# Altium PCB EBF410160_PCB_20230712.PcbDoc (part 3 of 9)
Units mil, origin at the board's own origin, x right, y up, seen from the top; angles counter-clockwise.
Board outline 5393.69 x 3858.26 mil, 6 copper layers (TOP, GND02, ART03, POW04, GND05, BOTTOM), stack 47.2 mil thick; 572 components, 434 nets, 2057 pads, 1177 vias.
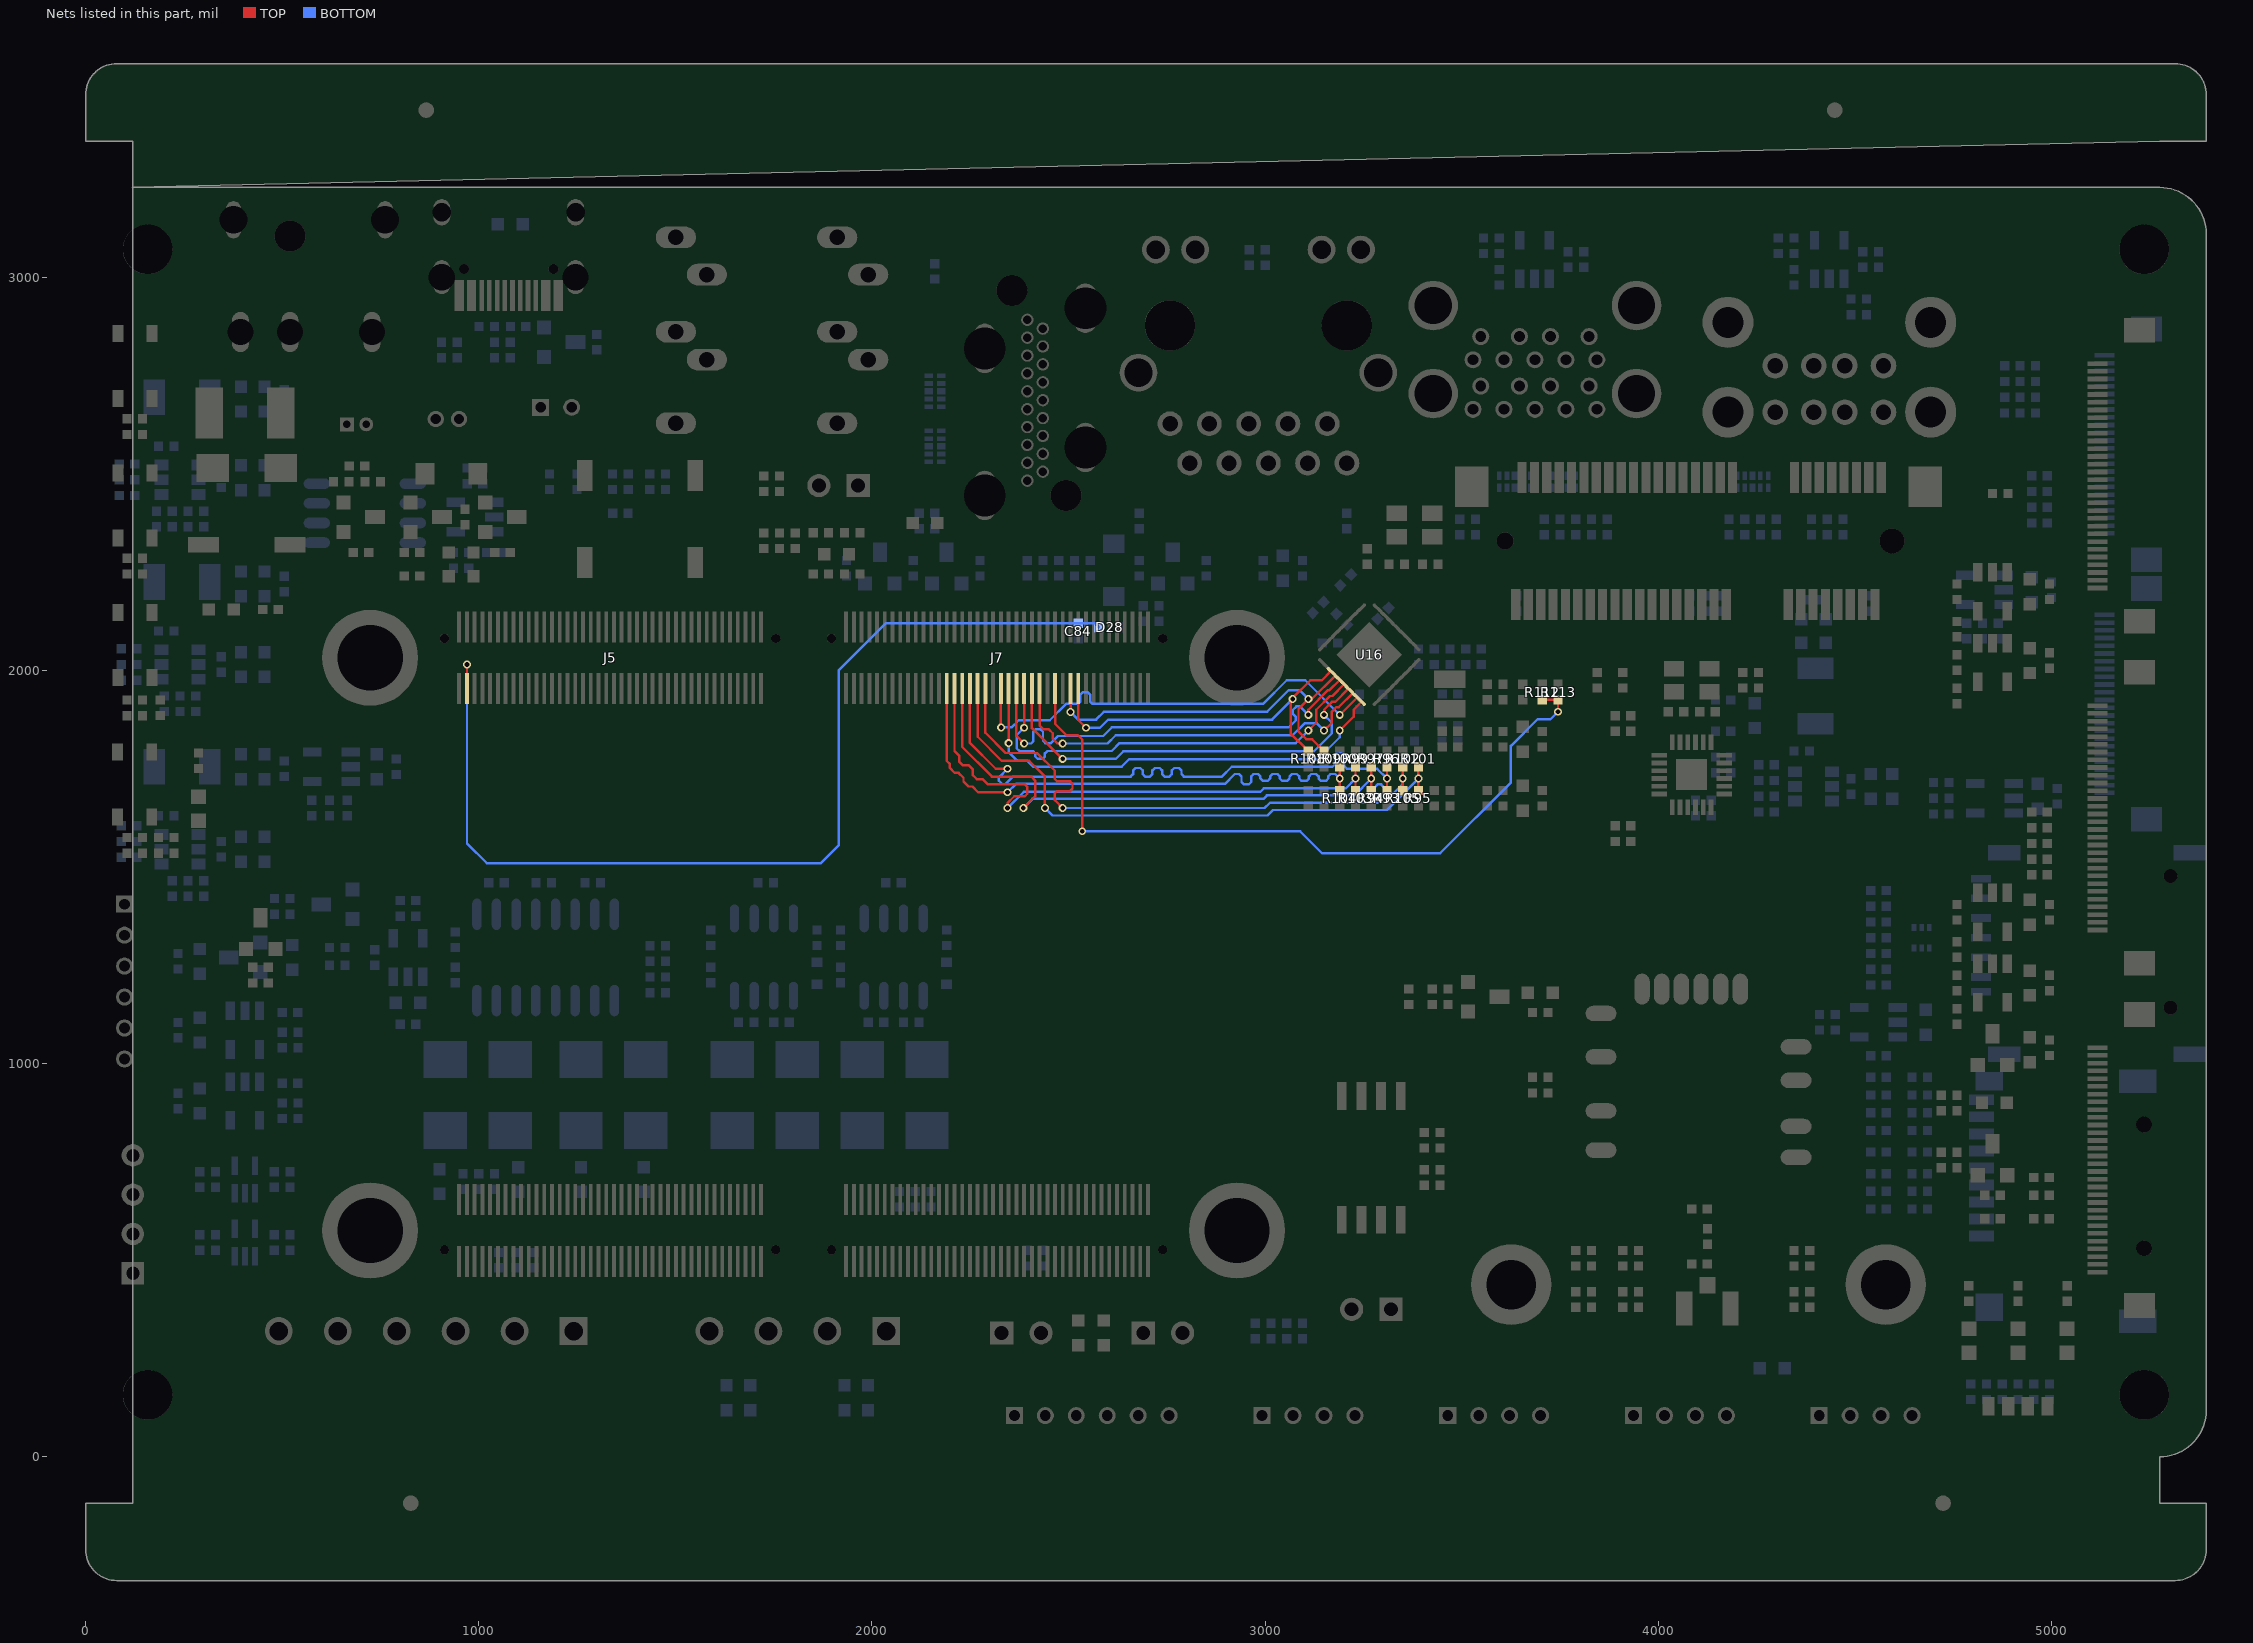
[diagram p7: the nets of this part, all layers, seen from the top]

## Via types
v1: diameter 20, hole 12, TOP to BOTTOM, 1177 vias

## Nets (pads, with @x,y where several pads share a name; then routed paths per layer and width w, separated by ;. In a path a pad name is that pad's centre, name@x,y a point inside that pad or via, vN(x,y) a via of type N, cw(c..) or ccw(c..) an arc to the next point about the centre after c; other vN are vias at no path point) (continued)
GMAC1_MCLKINOUT_M1: J7.56 R112.1 R113.1 | length 1915.2
  TOP w6.16: J7.56@2465.75,1953.5 2465.75,1864.25 2494.95,1835.05 2523.84,1835.05 2535,1823.89 v1(2535,1591) ; R112.1@3705,1925.32 R113.1@3745,1925.32 v1(3745,1895)
  BOTTOM w6.16: v1(2535,1591) 3089,1591 3145,1535 3445,1535 3625,1715 3625,1808.02 3692.91,1875.92 3725.92,1875.92 v1(3745,1895)
GMAC1_MDC_M1: J7.62 R108.2 U16.13 | length 945.1
  TOP w6.16: J7.62@2524.8,1953.5 2524.8,1873.82 v1(2544.49,1854.13) ; R108.2@3110,1794.68 3065,1839.68 3065,1922.05 v1(3070,1927.05) 3070,1930 3115,1975 3144.32,1975 U16.13@3167.56,1998.24
  BOTTOM w6.16: v1(2544.49,1854.13) 2580,1854.13 2600.87,1875 3017.95,1875 v1(3070,1927.05)
GMAC1_MDIO_M1: J7.60 R109.2 U16.14 | length 984.6
  TOP w6.16: v1(2505.12,1894.13) J7.60@2505.12,1953.5 ; R109.2@3150,1794.68 3119.68,1825 3105,1825 3085,1845 3085,1902.05 v1(3110,1927.05) 3118.65,1927.05 U16.14@3178.7,1987.1
  BOTTOM w6.16: v1(2505.12,1894.13) 2524.25,1875 2570,1875 2590,1895 3005,1895 3060,1950 3087.05,1950 v1(3110,1927.05)
GMAC1_RSTN: C84.1 D28.1 J5.4 | length 2661.6
  TOP w6.16: J5.4@969.68,1953.5 969.68,1979.68 970,1980 v1(970,2015)
  BOTTOM w6.16: v1(970,2015) 970,1560 1020,1510 1870,1510 1915,1555 1915,2000 2034.68,2119.68 C84.1@2525,2119.68 2567.37,2119.68 D28.1@2577.05,2110
GMAC1_RXCLK_M1: J7.36 R95.2 R101.1 | length 1472.9
  TOP w6.16: J7.36@2268.9,1953.5 2268.9,1831.1 2330,1770 2400,1770 2440,1730 v1(2440,1650) ; R95.2@3390,1694.68 v1(3390,1725) R101.1@3390,1755.32
  BOTTOM w6.16: v1(2440,1650) 2459.08,1630.92 3005.92,1630.92 3020,1645 3310,1645 v1(3390,1725)
GMAC1_RXD0_M1: J7.34 R93.2 R96.1 | length 1528.3
  TOP w6.16: J7.34@2249.21,1953.5 2249.21,1815.79 2315,1750 v1(2345,1750) ; R93.2@3310,1694.68 v1(3310,1725) R96.1@3310,1755.32
  BOTTOM w6.16: v1(2345,1750) 2322.94,1727.94 2322.94,1719.23 2331.16,1711.01 2339.87,1711.01 2358.86,1730 2657.92,1730 2664.08,1736.16 2664.08,1745.62 2670.24,1751.78 2682.56,1751.78 2688.72,1745.62 2688.72,1736.16 2694.88,1730 2707.2,1730 2713.36,1736.16 2713.36,1745.62 2719.52,1751.78 2731.84,1751.78 2738,1745.62 2738,1736.16 2744.16,1730 2756.48,1730 2762.64,1736.16 2762.64,1745.62 2768.8,1751.78 2781.12,1751.78 2787.28,1745.62 2787.28,1736.16 2793.44,1730 2890,1730 2915,1755 3171.14,1755 3177.3,1761.16 3177.3,1783.84 3183.45,1790 3195.78,1790 3201.93,1783.84 3201.93,1756.16 3208.09,1750 3285,1750 v1(3310,1725)
GMAC1_RXD1_M1: J7.32 R94.2 R97.1 | length 1428
  TOP w6.16: J7.32@2229.53,1953.5 2229.53,1805.47 2305,1730 2405,1730 2415,1720 2415,1680 v1(2385,1650) ; R94.2@3270,1694.68 v1(3270,1725) R97.1@3270,1755.32
  BOTTOM w6.16: v1(2385,1650) 2408.04,1673.04 2995.77,1673.04 3004.69,1681.96 3226.96,1681.96 v1(3270,1725)
GMAC1_RXD2_M1: J7.30 R99.1 R103.1 | length 1465.9
  TOP w6.16: J7.30@2209.84,1953.5 2209.84,1795.16 2221.76,1783.24 2221.76,1768.24 2231.68,1758.32 2240.39,1758.32 2246.68,1758.32 2256.61,1748.39 2256.61,1733.4 2266.53,1723.47 2275.24,1723.47 2281.53,1723.47 2295,1710 2388.84,1710 2395,1703.84 2395,1686.16 2388.84,1680 2361.99,1680 2345,1663.02 v1(2345,1650) ; R103.1@3230,1694.68 v1(3230,1725) R99.1@3230,1755.32
  BOTTOM w6.16: v1(2345,1650) 2386.52,1691.52 2988.11,1691.52 2997.03,1700.44 3205.44,1700.44 v1(3230,1725)
GMAC1_RXD3_M1: J7.28 R100.1 R104.1 | length 1434.6
  TOP w6.16: J7.28@2190.16,1953.5 2190.16,1769.84 2198.05,1761.95 2198.05,1751.95 2210.47,1739.53 2220.47,1739.53 2232.9,1727.1 2232.9,1717.1 2245.32,1704.68 2255.32,1704.68 2270,1690 v1(2345,1690) ; R104.1@3190,1694.68 v1(3190,1725) R100.1@3190,1755.32
  BOTTOM w6.16: v1(2345,1690) 2366.52,1711.52 2897.66,1711.52 2922.66,1736.52 2933.82,1736.52 2939.97,1730.36 2939.97,1716.16 2946.14,1710 2958.45,1710 2964.61,1716.16 2964.61,1730.36 2970.78,1736.52 2981.93,1736.52 2988.09,1730.36 2988.09,1725.08 2994.26,1718.92 3006.57,1718.92 3012.74,1725.08 3012.74,1730.36 3018.89,1736.52 3031.22,1736.52 3037.38,1730.36 3037.38,1725.08 3043.53,1718.92 3055.86,1718.92 3062.01,1725.08 3062.01,1730.36 3068.18,1736.52 3080.49,1736.52 3086.66,1730.36 3086.66,1725.08 3092.82,1718.92 3105.14,1718.92 3111.3,1725.08 3111.3,1730.36 3117.45,1736.52 3129.78,1736.52 3135.93,1730.36 3135.93,1725.08 3142.09,1718.92 3154.41,1718.92 3160.57,1725.08 3160.57,1730.36 3166.74,1736.52 3178.48,1736.52 v1(3190,1725)
GMAC1_RXDV_CRS_M1: J7.38 R102.1 R105.1 | length 1530.6
  TOP w6.16: J7.38@2288.58,1953.5 2288.58,1841.42 2340,1790 2420,1790 2465,1745 2465,1723.84 2471.16,1717.68 2503.84,1717.68 2510,1711.52 2510,1699.2 2503.84,1693.04 2471.16,1693.04 2465,1686.88 2465,1670 v1(2485,1650) ; R105.1@3350,1694.68 v1(3350,1725) R102.1@3350,1755.32
  BOTTOM w6.16: v1(2485,1650) 2998.86,1650 3012.34,1663.48 3286.34,1663.48 3292.5,1669.64 3292.5,1677.5 3277.44,1692.56 3277.44,1701.28 3286.16,1710 3295,1710 3317.57,1687.43 3326.28,1687.43 3350,1711.16 v1(3350,1725)
GMAC1_TXCLK_M1: J7.44 U16.20 | length 1163.3
  TOP w6.16: v1(2347.64,1815) J7.44@2347.64,1953.5 ; v1(3190,1847.05) 3225,1882.05 3225,1899.78 U16.20@3245.51,1920.29
  BOTTOM w6.16: v1(2347.64,1815) 2347.64,1792.36 2370,1770 2395,1770 2410,1755 2635,1755 2654.08,1774.08 3134.08,1774.08 3190,1830 v1(3190,1847.05)
GMAC1_TXD0_M1: J7.52 U16.18 | length 1003.3
  TOP w6.16: J7.52@2426.38,1953.5 2426.38,1859.76 2436.13,1850 2450,1850 2460,1840 2460,1826.13 2472.01,1814.13 v1(2485,1814.13) ; v1(3150,1847.05) 3170,1867.05 3170,1895.48 3180.65,1906.13 3186.81,1906.13 U16.18@3223.24,1942.56
  BOTTOM w6.16: v1(2485,1814.13) 2599.13,1814.13 2620,1835 3070,1835 3101.13,1866.13 3130.92,1866.13 v1(3150,1847.05)
GMAC1_TXD1_M1: J7.50 U16.17 | length 1075.4
  TOP w6.16: J7.50@2406.69,1953.5 2406.69,1853.31 v1(2485,1775) ; v1(3150,1887.05) 3150,1900 3170,1920 3178.4,1920 U16.17@3212.1,1953.7
  BOTTOM w6.16: v1(2485,1775) 2620,1775 2639.4,1794.4 3124.33,1794.4 3170,1840.07 3170,1867.05 v1(3150,1887.05)
GMAC1_TXD2_M1: J7.48 U16.16 | length 1110.5
  TOP w6.16: v1(2387.01,1854.13) J7.48@2387.01,1953.5 ; v1(3110,1847.05) 3130,1867.05 3130,1900 3165,1935 3171.13,1935 U16.16@3200.97,1964.84
  BOTTOM w6.16: v1(2387.01,1854.13) 2367.93,1835.05 2367.93,1802.07 2375,1795 2409.2,1795 2415.36,1788.84 2415.36,1781.16 2421.51,1775 2433.84,1775 2439.99,1781.16 2439.99,1788.84 2446.16,1795 2610,1795 2630,1815 3077.95,1815 v1(3110,1847.05)
GMAC1_TXD3_M1: J7.46 U16.15 | length 1126.4
  TOP w6.16: J7.46@2367.32,1953.5 2367.32,1833.82 v1(2387.01,1814.13) ; v1(3110,1887.05) 3110,1900 3160,1950 3163.87,1950 U16.15@3189.84,1975.96
  BOTTOM w6.16: v1(2387.01,1814.13) 2405,1814.13 2410,1819.13 2410,1843.84 2416.16,1850 2428.84,1850 2435,1843.84 2435,1821.16 2441.16,1815 2455,1815 2473.21,1833.21 2588.21,1833.21 2610,1855 3060,1855 3078.14,1873.14 3078.14,1881.86 3069.87,1890.13 3069.87,1898.84 3079.69,1908.65 3088.4,1908.65 v1(3110,1887.05)
GMAC1_TXEN_M1: J7.42 U16.19 | length 1154.6
  TOP w6.16: J7.42@2327.95,1953.5 2327.95,1855.61 v1(2328.56,1855) ; v1(3190,1887.05) U16.19@3234.37,1931.43
  BOTTOM w6.16: v1(2328.56,1855) 2355,1855 2373.21,1873.21 2452.13,1873.21 2493.92,1915 2524.07,1915 2530.24,1921.16 2530.24,1938.84 2536.39,1945 2548.72,1945 2554.88,1938.84 2554.88,1921.16 2561.03,1915 2995,1915 3055,1975 3102.05,1975 v1(3190,1887.05)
